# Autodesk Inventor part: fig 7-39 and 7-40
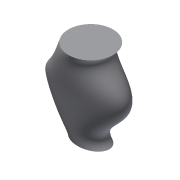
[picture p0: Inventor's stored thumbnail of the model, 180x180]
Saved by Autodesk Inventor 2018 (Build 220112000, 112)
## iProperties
Shininess: 64.0
Length Units: 11269
Angle Units: 11279
Time Units: 11290
Mass Units: 11283
Length Display Precision: 3
Angle Display Precision: 2
Compacted: True
Part Number: fig 7-39 and 7-40
Document SubType Name: Modeling
Created: 2002-12
Designer: deepak
Density: 1 g/cm^3
Material: Generic
Appearance: Default
Density: 0.0
Volumn: 0.0
Area: 0.0
PropertySet Name: Model Information
Control State: 0
Master: False
Checked Out: False
Author: deepak
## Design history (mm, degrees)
sketch "Sketch1"
  geometry: 2 further points; 1 other entity
  constraints: 1 coincident, 3 other
workplane "Work Plane1"
workplane "Work Plane2"
sketch "Sketch3"
  geometry: C1 r 60 at (0, 0); 1 further point
  constraints: 1 centre point, 1 coincident, 1 other
sketch "Sketch4"
  geometry: 8 further points
  constraints: 8 other
sketch "Sketch5"
  geometry: 6 further points
  constraints: 6 other
sketch "Sketch6"
  geometry: 6 further points
  constraints: 6 other
  dimensions: "d20" = 35 distance of point (0, 0) point (-35, 0); "d21" = 0 vertical distance of point (0, 0) point (-35, 0); "d22" = 225 vertical distance of point (0, 0) point (-60, 225); "d23" = 60 horizontal distance of point (0, 0) point (-60, 225); "d24" = 100 horizontal distance of point (0, 0) point (-100, 125); "d25" = 125 vertical distance of point (0, 0) point (-100, 125)
loft "Loft3" dims "d42" = 0, "d43" = 90 deg, "d44" = 0, "d45" = 90 deg, "d46" = 0, "d47" = 90 deg, "d48" = 0, "d49" = 90 deg
node "Sketch7"
sketch "Sketch8"
  geometry: 1 further point
body "Solid1"
other parameters: "d5" = 125
